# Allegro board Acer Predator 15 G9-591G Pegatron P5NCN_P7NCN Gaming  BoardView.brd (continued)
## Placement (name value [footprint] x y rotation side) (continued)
C7829  -  [VX_C0402_SMALL]  139.24 127.78 270 bottom
C7830  -  [VX_C0402_SMALL]  146.8 143.74 270 top
C7831  -  [VX_C0402_SMALL]  146.71 127.85 180 top
C7832  -  [VX_C0402_SMALL]  149.53 123.33 0 top
C7833  -  [VX_C0402_SMALL]  149.53 121.93 0 top
C7834  -  [VX_C0402_SMALL]  150.84 123.99 270 top
C7835  -  [VX_C0402_SMALL]  154.36 127.65 0 top
C7836  -  [VX_C0603_SMALL]  155.96 120.46 0 bottom
C7837  -  [VX_C0603_SMALL]  155.88 119.85 0 top
C7900  -  [VX_C0402_SMALL]  118.54 99.17 270 top
C7903  -  [VX_C0402_SMALL]  125.2 105.93 0 top
C7904  -  [VX_C0402_SMALL]  130.1 99.33 90 top
C7905  -  [VX_C0402_SMALL]  125.2 107.28 0 top
C7906  -  [VX_C0402_SMALL]  127.31 114.95 270 bottom
C7907  -  [VX_C0402_SMALL]  132 99.33 90 top
C7908  -  [VX_C0402_SMALL]  136.07 99.28 90 top
C7909  -  [VX_C0402_SMALL]  139.29 102.51 90 top
C7910  -  [VX_C0402_SMALL]  133.53 102.99 270 top
C7911  -  [VX_C0402_SMALL]  134.67 99.33 90 top
C7912  -  [VX_C0402_SMALL]  128.32 99.33 90 top
C7913  -  [VX_C0402_SMALL]  133.76 108.94 90 top
C7914  -  [VX_C0402_SMALL]  143.74 128.95 180 top
C7915  -  [VX_C0402_SMALL]  133.53 101.36 90 top
C7916  -  [VX_C0402_SMALL]  128.14 114.95 270 bottom
C7917  -  [VX_C0402_SMALL]  125.53 101.61 0 top
C7918  -  [VX_C0402_SMALL]  127.84 105.71 270 top
C7919  -  [VX_C0402_SMALL]  125.63 100.34 0 top
C7920  -  [VX_C0603_SMALL]  135.22 107.21 90 top
C7921  -  [VX_C0603_SMALL]  131.33 110.97 90 top
C7922  -  [VX_C0402_SMALL]  122.89 99.18 90 top
C7923  -  [VX_C0402_SMALL]  114.22 104.41 270 top
C7924  -  [VX_C0402_SMALL]  119.99 103.42 90 top
C7925  -  [VX_C0402_SMALL]  121.77 110.43 270 top
C7926  -  [VX_C0402_SMALL]  118.29 101.49 90 top
C7927  -  [VX_C0402_SMALL]  114.43 106 0 top
C7928  -  [VX_C0402_SMALL]  115.28 112.23 270 top
C7929  -  [VX_C0402_SMALL]  141.59 141.99 180 top
C7930  -  [VX_C0402_SMALL]  118.29 104.54 270 top
C7931  -  [VX_C0402_SMALL]  119.94 101.57 90 top
C7932  -  [VX_C0402_SMALL]  112.71 109.73 90 top
C7933  -  [VX_C0402_SMALL]  114.52 107.81 0 top
C7934  -  [VX_C0402_SMALL]  119.94 99.2 90 top
C7935  -  [VX_C0402_SMALL]  124.41 99.18 90 top
C7936  -  [VX_C0603_SMALL]  111.94 100.6 270 bottom
C7937  -  [VX_C0603_SMALL]  111.9 111.14 270 bottom
C8000  -  [VX_C0402_SMALL]  11.23 178.96 180 top
C8001  -  [VX_C0402_SMALL]  5 175.78 180 top
C8002  -  [VX_C0402_SMALL]  7.29 178.2 0 top
C8003  -  [VX_C0402_SMALL]  5 174.89 180 top
C8004  -  [VX_C0402_SMALL]  4.71 175.13 90 bottom
C8005  -  [VX_C0402_SMALL]  2.59 176.42 0 bottom
C8006  -  [VX_C0402_SMALL]  2.85 175.78 180 top
C8007  -  [VX_C0402_SMALL]  2.59 178.45 0 top
C8008  -  [VX_C0402_SMALL]  2.59 179.34 0 top
C8009  -  [VX_C0402_SMALL]  16.58 180.08 0 bottom
C8010  -  [VX_C0402_SMALL]  12.75 184.8 90 bottom
C8011  -  [VX_C0402_SMALL]  6.53 171.59 270 bottom
C8012  -  [VX_C0402_SMALL]  2.59 175.53 0 bottom
C8013  -  [VX_C0402_SMALL]  20.88 176.93 270 bottom
C8014  -  [VX_C0402_SMALL]  15.42 184.8 90 bottom
C8015  -  [VX_C0402_SMALL]  15.81 181.05 0 bottom
C8016  -  [VX_C0402_SMALL]  16.31 184.8 90 bottom
C8017  -  [VX_C0402_SMALL]  8.94 171.59 270 bottom
C8018  -  [VX_C0402_SMALL]  10.72 171.39 90 bottom
C8019  -  [VX_C0402_SMALL]  7.42 171.59 270 bottom
C8020  -  [VX_C0402_SMALL]  1.58 171.08 90 bottom
C8021  -  [VX_C0402_SMALL]  17.69 177.99 270 bottom
C8022  -  [VX_C0402_SMALL]  17.2 176.54 0 bottom
C8023  -  [VX_C0402_SMALL]  18.78 176.54 0 bottom
C8024  -  [VX_C0402_SMALL]  10.03 176.04 270 top
C8025  -  [VX_C0402_SMALL]  8.94 177.31 0 top
C8026  -  [VX_C0402_SMALL]  3.73 171.08 270 bottom
C8027  -  [VX_C0402_SMALL]  21.13 175.15 90 bottom
C8028  -  [VX_C0402_SMALL]  20.24 175.15 270 bottom
C8029  -  [VX_C0402_SMALL]  21.6 173.88 180 bottom
C8030  -  [VX_C0402_SMALL]  18.85 174.64 180 bottom
C8031  -  [VX_C0402_SMALL]  17.07 170.7 90 bottom
C8032  -  [VX_C0402_SMALL]  15.93 171.97 0 bottom
C8033  -  [VX_C0402_SMALL]  13.16 178.15 0 top
C8034  -  [VX_C0402_SMALL]  25.71 175.53 180 bottom
C8035  -  [VX_C0402_SMALL]  15.16 173.37 90 bottom
C8036  -  [VX_C0402_SMALL]  23.39 175.27 180 bottom
C8050  -  [VX_C0805_H57_SMALL]  37.9 173.24 90 bottom
C8051  -  [VX_C0805_H57_SMALL]  37.14 173.24 90 top
C8052  -  [VX_C0805_H57_SMALL]  38.91 173.24 90 top
C8053  -  [VX_C0402_SMALL]  39.29 172.99 90 bottom
C8054  -  [VX_C0402_SMALL]  42.72 173.88 270 bottom
C8055  -  [VX_C0402_SMALL]  31.8 174.13 270 bottom
C8056  -  [VX_C0805_H57_SMALL]  26.09 172.68 90 top
C8057  -  [VX_C0805_H57_SMALL]  27.86 172.68 90 top
C8058  -  [VX_C0805_H57_SMALL]  28.12 172.68 90 bottom
C8059  -  [VX_C0402_SMALL]  29.52 172.61 90 bottom
C8060  -  [VX_C0402_SMALL]  65.71 169.81 270 bottom
C8061  -  [VX_C0805_H57_SMALL]  60.12 168.54 90 top
C8062  -  [VX_C0805_H57_SMALL]  61.9 168.54 90 top
C8063  -  [VX_C0805_H57_SMALL]  60.63 168.42 90 bottom
C8064  -  [VX_C0402_SMALL]  62.03 168.16 90 bottom
C8065  -  [VX_C0402_SMALL]  44.12 174.64 0 bottom
C8066  -  [VX_C0402_SMALL]  33.2 174.77 0 bottom
C8067  -  [VX_C0402_SMALL]  66.3 172.45 0 bottom
C8068  -  [VX_C0402_H26_SMALL]  46.03 174 90 bottom
C8069  -  [VX_C0402_H26_SMALL]  34.85 173.88 90 bottom
C8070  -  [VX_C0402_H26_SMALL]  70.64 168.79 90 top
C8071  -  [VX_C0603_SMALL]  43.1 170.19 180 bottom
C8072  -  [VX_C0603_SMALL]  30.15 170.45 180 bottom
C8073  -  [VX_C0603_SMALL]  60.38 163.67 180 top
C8074  -  [VX_C0603_H39_SMALL]  57.96 160.29 270 top
C8075  -  [VX_C0603_H39_SMALL]  61.9 158 180 bottom
C8076  -  [VX_C0603_H39_SMALL]  61.9 156.73 180 bottom
C8077  -  [VX_C0603_H39_SMALL]  59.23 160.29 270 top
C8078  -  [VX_C0603_H39_SMALL]  52.76 138.83 180 top
C8079  -  [VX_C0603_H39_SMALL]  45.09 142.59 0 top
C8080  -  [VX_C0603_H39_SMALL]  47.7 142.64 180 top
C8081  -  [VX_C0603_H39_SMALL]  52.76 141.37 180 top
C8082  -  [VX_C0603_H39_SMALL]  47.7 141.37 180 top
C8083  -  [VX_C0603_H39_SMALL]  49.96 142.64 0 top
C8084  -  [VX_C0603_H39_SMALL]  52.76 142.64 180 top
C8085  -  [VX_C0603_H39_SMALL]  49.96 141.37 0 top
C8086  -  [VX_C0402_SMALL]  68.12 168.92 90 bottom
C8087  -  [VX_C0805_H57_SMALL]  89.84 171.59 90 bottom
C8088  -  [VX_C0805_H57_SMALL]  91.62 171.59 90 bottom
C8089  -  [VX_C0805_H57_SMALL]  93.4 171.59 90 bottom
C8090  -  [VX_C0402_SMALL]  88.19 170.96 180 bottom
C8091  -  [VX_C0603_H39_SMALL]  40.44 164.48 270 bottom
C8092  -  [VX_C0603_H39_SMALL]  52.88 158 270 top
C8093  -  [VX_C0603_H39_SMALL]  49.33 154.83 0 top
C8094  -  [VX_C0603_H39_SMALL]  60.5 160.03 270 bottom
C8095  -  [VX_C0603_H39_SMALL]  61.77 160.03 270 bottom
C8096  -  [VX_C0603_H39_SMALL]  45.09 141.32 0 top
C8097  -  [VX_C0603_H39_SMALL]  45.09 140.05 0 top
C8098  -  [VX_C0603_H39_SMALL]  41.68 164.48 270 bottom
C8099  -  [VX_C0603_H39_SMALL]  47.7 138.83 180 top
C8100  -  [VX_C0402_SMALL]  218.87 70.5 90 top
C8101  -  [VX_C0603_SMALL]  217.73 70.5 270 top
C8102  -  [VX_C0805_H57_SMALL]  206.38 57.77 0 bottom
C8103  -  [VX_C0402_SMALL]  206.4 59.27 0 bottom
C8104  -  [VX_C0805_H57_SMALL]  217.22 64.28 270 bottom
C8105  -  [VX_C0805_H57_SMALL]  215.44 64.28 270 bottom
C8106  -  [VX_C0402_SMALL]  218.49 64.28 270 bottom
C8107  -  [VX_C0603_SMALL]  222.81 74.69 180 top
C8108  -  [VX_C0603_SMALL]  213.54 74.82 180 top
C8109  -  [VX_C0402_SMALL]  232 81.52 270 bottom
C8110  -  [VX_C0402_SMALL]  193.22 71.64 0 bottom
C8111  -  [VX_C0402_SMALL]  220.93 69.82 90 bottom
C8112  -  [VX_C0402_SMALL]  203.38 63.77 180 bottom
C8113  -  [VX_C0402_SMALL]  220.4 78.12 0 top
C8114  -  [VX_C0402_SMALL]  216.33 77.99 0 top
C8115  -  [VX_C0402_SMALL]  220.78 80.66 270 top
C8116  -  [VX_C0402_SMALL]  215.95 80.53 90 top
C8117  -  [VX_C0402_SMALL]  218.24 78.12 0 top
C8118  -  [VX_C0402_SMALL]  213.16 77.36 180 top
C8119  -  [VX_C0603_SMALL]  241.73 65.8 90 top
C8120  -  [VX_C0603_SMALL]  244.78 68.34 0 top
C8121  -  [VX_C0603_SMALL]  246.3 65.42 90 top
C8122  -  [VX_C0603_SMALL]  247.83 68.34 0 top
C8123  -  [VX_C0603_SMALL]  251 65.55 90 top
C8124  -  [VX_C0402_SMALL]  213.9 48.31 180 bottom
C8125  -  [VX_C0402_SMALL]  213.56 40.75 180 bottom
C8126  -  [VX_C0402_SMALL]  199.8 65.98 90 top
C8127  -  [VX_C0402_SMALL]  208.48 79.57 180 top
C8128  -  [VX_C0402_SMALL]  213.56 41.62 180 bottom
C8129  -  [VX_C0402_SMALL]  213.9 49.46 180 bottom
C8130  -  [VX_C0402_SMALL]  236.09 65.9 90 top
C8131  -  [VX_C0402_SMALL]  236.98 65.9 90 top
C8202  -  [VX_C0402_SMALL]  135.81 72.36 270 bottom
C8203  -  [VX_C0805_H57_SMALL]  128.6 66.57 0 bottom
C8205  -  [VX_C0603_SMALL]  136.7 68.09 270 bottom
C8206  -  [VX_C0402_SMALL]  136.96 75.28 0 bottom
C8207  -  [VX_C0603_SMALL]  142.55 70.45 270 bottom
C8208  -  [VX_C0402_SMALL]  140.39 76.55 0 bottom
C8209  -  [VX_C0603_H39_SMALL]  154.91 72.99 90 bottom
C8210  -  [VX_C0603_H39_SMALL]  153.7 72.99 90 bottom
C8211  -  [VX_C0603_H39_SMALL]  152.48 72.99 90 bottom
C8212  -  [VX_C0603_H39_SMALL]  147.5 66.9 180 bottom
C8213  -  [VX_C0603_H39_SMALL]  151.26 72.99 90 bottom
C8214  -  [VX_C0402_SMALL]  134.93 72.36 270 bottom
C8215  -  [VX_C0402_SMALL]  127.81 67.96 0 bottom
C8216  -  [VX_C0402_SMALL]  146.73 69.02 0 bottom
C8300  -  [VX_C0603_SMALL]  132.26 58.56 0 top
C8301  -  [VX_C0603_SMALL]  132.26 57.29 0 top
C8302  -  [VX_C0402_SMALL]  130.73 59.7 0 top
C8303  -  [VX_C0402_SMALL]  136.13 59.02 180 top
C8304  -  [VX_C0402_SMALL]  125.13 70.39 90 bottom
C8305  -  [VX_C0402_SMALL]  124.24 70.39 90 bottom
C8306  -  [VX_C0805_H57_SMALL]  128.07 67.32 90 top
C8307  -  [VX_C0805_H57_SMALL]  126.4 69.88 90 bottom
C8308  -  [VX_C0603_SMALL]  130.61 61.23 270 top
C8309  -  [VX_C0603_SMALL]  130.48 65.42 0 top
C8310  -  [VX_C0402_SMALL]  137.85 64.78 270 top
C8311  -  [VX_C0603_H39_SMALL]  115.37 74.06 90 top
C8312  -  [VX_C0603_H39_SMALL]  111.56 74.06 90 top
C8313  -  [VX_C0603_H39_SMALL]  115.77 68.7 270 top
C8314  -  [VX_C0402_SMALL]  123.38 70.39 90 bottom
C8315  -  [VX_C0603_H39_SMALL]  114.1 74.06 90 top
C8316  -  [VX_C0603_H39_SMALL]  112.83 74.06 90 top
C8317  -  [VX_C0603_H39_SMALL]  117.04 68.7 270 top
C8318  -  [VX_C0402_SMALL]  134.93 66.56 0 top
C8319  -  [VX_C0402_SMALL]  138.1 61.61 180 top
C8320  -  [VX_C0402_SMALL]  138.1 58.94 0 top
C8321  -  [VX_C0402_SMALL]  139.88 58.94 180 top
C8322  -  [VX_C0402_SMALL]  138.1 62.5 180 top
C8323  -  [VX_C0402_SMALL]  119.43 21.89 0 top
C8324  -  [VX_C0402_SMALL]  136.83 61.86 180 bottom
C8325  -  [VX_C0402_SMALL]  108.66 75.25 180 top
C8326  -  [VX_C0402_SMALL]  108.66 74.36 180 top
C8327  -  [VX_C0402_SMALL]  132.21 56.25 180 top
C8328  -  [VX_C0402_SMALL]  132.21 55.36 180 top
C8400  -  [VX_C0402_SMALL]  168.2 26 90 top
C8401  -  [VX_C0603_SMALL]  171.7 27.95 0 top
C8402  -  [VX_C0402_SMALL]  174.12 22.78 90 top
C8403  -  [VX_C0402_SMALL]  174.63 25.59 180 top
C8404  -  [VX_C0603_SMALL]  175.31 26.68 0 top
C8405  -  [VX_C0402_SMALL]  170.08 28.31 270 top
C8406  -  [VX_C0402_SMALL]  167.06 29.56 180 top
C8700  -  [VX_C0402_SMALL]  154.36 87.98 90 bottom
C8701  -  [VX_C0402_SMALL]  119.69 79.72 90 top
C8702  -  [VX_C0805_H57_SMALL]  122.23 79.21 90 top
C8703  -  [VX_C0603_SMALL]  120.7 79.6 270 top
C8704  -  [VX_C0805_H57_SMALL]  124 79.21 90 top
C8706  -  [VX_C0402_SMALL]  146.45 83.48 180 bottom
C8707  -  [VX_C0603_SMALL]  148.13 88.61 90 bottom
C8708  -  [VX_C0402_SMALL]  120.13 80.47 0 bottom
C8709  -  [VX_C0402_SMALL]  153.09 85.24 0 bottom
C8710  -  [VX_C0603_H39_SMALL]  144.27 106.77 180 top
C8711  -  [VX_C0603_H39_SMALL]  98.7 108.12 0 top
C8712  -  [VX_C0603_H39_SMALL]  98.7 106.85 0 top
C8713  -  [VX_C0603_H39_SMALL]  138.61 92.34 90 top
C8714  -  [VX_C0603_H39_SMALL]  98.68 109.39 0 top
C8715  -  [VX_C0603_H39_SMALL]  97.49 148.71 0 top
C8716  -  [VX_C0603_H39_SMALL]  134.8 92.34 90 top
C8717  -  [VX_C0603_H39_SMALL]  136.07 92.34 90 top
C8718  -  [VX_C0603_H39_SMALL]  137.34 92.34 90 top
C8719  -  [VX_C0603_H39_SMALL]  144.27 105.5 180 top
C8720  -  [VX_C0603_H39_SMALL]  144.32 109.31 180 top
C8721  -  [VX_C0603_H39_SMALL]  144.27 108.04 180 top
C8722  -  [VX_C0603_H39_SMALL]  144.27 104.23 180 top
C8723  -  [VX_C0402_SMALL]  158.67 83.28 90 bottom
C8724  -  [VX_C0402_SMALL]  156.06 79.9 180 bottom
C8725  -  [VX_C0402_SMALL]  157.02 83.78 270 bottom
C8726  -  [VX_C0402_SMALL]  156.13 84.6 270 bottom
C8727  -  [VX_C0603_SMALL]  149.78 80.28 270 top
C8728  -  [VX_C0402_SMALL]  132.39 81.75 90 top
C8729  -  [VX_C0603_SMALL]  132.86 76.69 180 top
C8730  -  [VX_C0805_H57_SMALL]  133.27 78.2 0 top
C8731  -  [VX_C0805_H57_SMALL]  133.27 79.98 0 top
C8733  -  [VX_C0402_SMALL]  145.6 78.53 270 bottom
C8735  -  [VX_C0402_SMALL]  137.62 76.67 90 bottom
C8736  -  [VX_C0402_SMALL]  143.04 95.26 270 top
C8737  -  [VX_C0402_SMALL]  156.9 105.88 180 top
C8738  -  [VX_C0603_SMALL]  157.15 101.19 0 top
C8739  -  [VX_C0805_H57_SMALL]  157.15 104.49 180 top
C8740  -  [VX_C0805_H57_SMALL]  157.15 102.66 180 top
C8741  -  [VX_C0402_H28_SMALL]  147.5 98.14 180 top
C8742  -  [VX_C0402_SMALL]  156 107.6 180 bottom
C8743  -  [VX_C0402_SMALL]  128.65 96.76 270 top
C8744  -  [VX_C0402_SMALL]  129.62 96.77 270 top
C8745  -  [VX_C0603_SMALL]  123.11 67.53 90 top
C8746  -  [VX_C0603_SMALL]  121.99 75.97 0 top
C8747  -  [VX_C0402_SMALL]  120.4 75.79 270 top
C8748  -  [VX_C0603_SMALL]  124.51 72.28 270 top
C8800  -  [VX_C0402_SMALL]  9.7 113.38 270 top
C8801  -  [VX_C0402_SMALL]  9.32 114.65 180 top
C8802  -  [VX_C0402_SMALL]  253.42 18.64 90 top
C8803  -  [VX_C0805_H57_SMALL]  222.94 16.35 90 top
C8804  -  [VX_C0402_SMALL]  228.8 17.29 270 top
C8806  -  [VX_C1206_H49]  8.05 109.29 270 top
C8807  -  [VX_C0402_SMALL]  224 33.75 180 top
C8808  -  [VX_C0402_SMALL]  223.24 32.48 270 top
C8809  -  [VX_C0402_SMALL]  224.64 32.48 270 top
C8810  -  [VX_C0402_SMALL]  229.69 17.29 90 top
C8811  -  [VX_C0805_H57_SMALL]  224.71 16.35 90 top
C8812  -  [VX_C0805_H57_SMALL]  226.49 16.35 90 top
C8813  -  [VX_C0402_SMALL]  227.89 17.32 90 top
C8814  -  [VX_C0402_SMALL]  218.49 29.94 90 top
C8815  -  [VX_C0402_SMALL]  214.55 29.38 180 top
C8816  -  [VX_C0603_SMALL]  225.6 29.76 180 top
C8817  -  [VX_C0402_SMALL]  227 28.59 180 top
C8818  -  [VX_C0805_H57_SMALL]  252.65 12.16 90 top
C8819  -  [VX_C0805_H57_SMALL]  249.1 12.16 90 top
C8820  -  [VX_C0805_H57_SMALL]  250.88 12.16 90 top
C8821  -  [VX_C0603_SMALL]  226.12 25.75 0 top
C8822  -  [VX_C0402_SMALL]  230.56 17.29 90 top
C8823  -  [VX_C0402_SMALL]  232.33 25.06 90 top
C8824  -  [VX_C0402_SMALL]  216.39 24.86 270 top
C8825  -  [VX_C0402_SMALL]  230.43 25.7 0 top
C8826  -  [VX_C0402_SMALL]  230.43 24.3 0 top
C8827  -  [VX_C0402_SMALL]  217.98 37.3 270 top
C8828  -  [VX_C0805_H57_SMALL]  219.25 44.42 180 bottom
C8829  -  [VX_C0402_SMALL]  221.03 39.08 90 bottom
C8830  -  [VX_C0402_SMALL]  218.62 36.54 90 bottom
C8831  -  [VX_C0402_SMALL]  214.55 28.54 0 top
C8832  -  [VX_C0402_SMALL]  221.71 32.99 90 bottom
C8900  -  [VX_C0402_SMALL]  162.02 85.26 90 top
C8901  -  [VX_C0805_H57_SMALL]  172.77 86.33 180 top
C8902  -  [VX_C0805_H57_SMALL]  160.71 84.88 90 top
C8903  -  [VX_C0402_SMALL]  176 83.28 180 top
C8904  -  [VX_C0402_SMALL]  178.99 81.55 180 top
C8905  -  [VX_C0402_SMALL]  159.18 95.98 270 top
C8906  -  [VX_C0402_SMALL]  172.1 83.02 180 top
C8907  -  [VX_C0402_SMALL]  178.73 88.49 90 top
C8908  -  [VX_C0402_SMALL]  184.96 85.23 180 top
C8909  -  [VX_C0402_SMALL]  185.03 83.35 180 top
C8910  -  [VX_C0603_SMALL]  175.31 87.39 270 top
C8912  -  [VX_C0402_SMALL]  179.79 88.46 270 top
C8915  -  [VX_C0402_SMALL]  180.63 88.14 270 top
C8916  -  [VX_C0402_SMALL]  143.45 121.14 180 top
C8917  -  [VX_C0402_SMALL]  160.07 87.85 90 bottom
C09100  -  [VX_C0201_H14]  33.45 136.87 0 top
C9100  -  [VX_C0402_SMALL]  141.58 65.6 180 bottom
C09101  -  [VX_C0201_H14]  28.5 143.65 0 top
C9101  -  [VX_C0402_H26_SMALL]  141.4 60.72 90 bottom
C9102  -  [VX_C0402_SMALL]  149.4 48.61 90 top
C09102  -  [VX_C0201_H14]  37.52 144.41 0 top
C09103  -  [VX_C0201_H14]  33.2 147.46 180 top
C9103  -  [VX_C0402_SMALL]  144.63 65.88 270 bottom
C9104  -  [VX_C0402_SMALL]  154.23 46.83 180 top
C09104  -  [VX_C0201_H14]  34.34 145.18 180 top
C09105  -  [VX_C0201_H14]  32.82 144.41 0 top
C9105  -  [VX_C0402_SMALL]  143.8 65.88 270 bottom
C09106  -  [VX_C0201_H14]  37.52 143.65 0 top
C09107  -  [VX_C0201_H14]  35.61 147.46 0 top
C9107  -  [VX_C0402_H26_SMALL]  146.23 62.96 90 bottom
C09108  -  [VX_C0201_H14]  37.92 147.46 180 top
C9108  -  [VX_C0402_SMALL]  144.22 59.5 180 bottom
C09109  -  [VX_C0201_H14]  37.52 145.18 0 top
C9109  -  [VX_C0402_SMALL]  142.62 59.5 0 bottom
C09110  -  [VX_C0201_H14]  38.28 136.84 0 top
C9110  -  [VX_C0402_SMALL]  146.23 61.36 270 bottom
C09111  -  [VX_C0201_H14]  38.28 136.08 0 top
C9111  -  [VX_C0402_SMALL]  195.9 70.75 270 bottom
C9112  -  [VX_C0402_SMALL]  198.55 66.05 180 top
C09112  -  [VX_C0201_H14]  40.82 136.16 0 top
C09113  -  [VX_C0201_H14]  39.04 143.65 180 top
C9113  -  [VX_C0402_SMALL]  193.07 66.69 270 top
C9114  -  [VX_C0402_SMALL]  195.76 70.63 270 top
C09114  -  [VX_C0201_H14]  33.45 134.58 0 top
C9115  -  [VX_C0402_SMALL]  193.22 68.47 90 top
C09115  -  [VX_C0201_H14]  30.66 135.27 180 top
C09116  -  [VX_C0201_H14]  28.5 149.37 180 top
C9116  -  [VX_C0402_SMALL]  195 63.9 90 top
C09117  -  [VX_C0201_H14]  33.2 149.37 180 top
C9117  -  [VX_C0402_SMALL]  195.89 63.9 90 top
C09118  -  [VX_C0201_H14]  40.31 149.37 0 top
C9118  -  [VX_C0402_SMALL]  220.65 86.12 180 bottom
C09119  -  [VX_C0201_H14]  28.5 142.13 0 top
C9119  -  [VX_C0402_SMALL]  216.26 88.03 180 bottom
C09120  -  [VX_C0201_H14]  30.02 142.89 180 top
C9120  -  [VX_C0402_SMALL]  220.65 84.85 180 bottom
C09121  -  [VX_C0201_H14]  37.52 142.89 0 top
C9121  -  [VX_C0402_SMALL]  218.26 82.59 0 bottom
C09122  -  [VX_C0201_H14]  28.5 145.18 0 top
C9122  -  [VX_C0402_SMALL]  217.86 88.03 0 bottom
C09123  -  [VX_C0201_H14]  34.34 142.89 180 top
C9123  -  [VX_C0402_SMALL]  214.17 84.98 0 bottom
C09124  -  [VX_C0201_H14]  33.45 135.35 0 top
C9124  -  [VX_C0402_SMALL]  214.17 85.99 0 bottom
C09125  -  [VX_C0201_H14]  36.25 135.4 180 top
C9125  -  [VX_C0402_SMALL]  216.56 82.59 180 bottom
C09126  -  [VX_C0201_H14]  36.25 134.67 180 top
C9126  -  [VX_C0402_SMALL]  237.54 63.9 0 top
C09127  -  [VX_C0201_H14]  32.82 142.89 0 top
C9127  -  [VX_C0402_SMALL]  239.32 61.08 180 top
C09128  -  [VX_C0201_H14]  28.5 144.41 0 top
C9128  -  [VX_C0402_SMALL]  233.17 61.25 0 bottom
C9129  -  [VX_C0402_SMALL]  239.32 61.99 180 top
C09129  -  [VX_C0201_H14]  37.92 149.37 180 top
C09130  -  [VX_C0201_H14]  32.82 143.65 0 top
C9130  -  [VX_C0402_SMALL]  235.13 63.9 180 top
C9131  -  [VX_C0402_SMALL]  237.67 59.22 0 top
C9132  -  [VX_C0402_SMALL]  235.26 59.22 180 top
C9133  -  [VX_C0402_SMALL]  196.52 82.14 270 top
C9134  -  [VX_C0402_SMALL]  198.17 82.14 270 top
C9200  -  [VX_C0402_SMALL]  136.45 49.98 0 top
C9400  -  [VX_C0402_SMALL]  81.08 158.13 90 bottom
C9401  -  [VX_C0805_H57_SMALL]  84.25 158.38 90 bottom
C9402  -  [VX_C0805_H57_SMALL]  82.47 158.38 90 bottom
C9403  -  [VX_C0402_SMALL]  79.55 154.4 0 bottom
C9405  -  [VX_C0603_SMALL]  73.17 160.87 0 bottom
C9406  -  [VX_C0603_H39_SMALL]  65.96 162.07 90 bottom
C9407  -  [VX_C0603_H39_SMALL]  70.92 162.07 90 bottom
C9408  -  [VX_C0603_H39_SMALL]  67.23 162.07 90 bottom
C9409  -  [VX_C0603_H39_SMALL]  68.5 162.07 90 bottom
C9410  -  [VX_C0603_H39_SMALL]  69.77 162.07 90 bottom
C9411  -  [VX_C0402_SMALL]  78.66 158 90 top
C9412  -  [VX_C0402_SMALL]  79.55 152.62 180 bottom
C9414  -  [VX_C0402_SMALL]  73.2 148.1 180 bottom
C9415  -  [VX_C0402_SMALL]  73.2 148.99 180 bottom
C9416  -  [VX_C0402_SMALL]  71.81 153 180 bottom
C9500  -  [VX_C0402_SMALL]  123.11 60.97 90 bottom
C9501  -  [VX_C0805_H57_SMALL]  126.16 60.97 90 bottom
C9502  -  [VX_C0805_H57_SMALL]  124.38 60.97 90 bottom
C9503  -  [VX_C0402_SMALL]  120.07 58.39 180 top
C9504  -  [VX_C0402_SMALL]  117.87 64.11 0 top
C9505  -  [VX_C0603_SMALL]  120.57 61.23 0 top
C9506  -  [VX_C0603_H39_SMALL]  109.02 65.67 90 top
C9507  -  [VX_C0603_H39_SMALL]  110.29 65.67 90 top
C9508  -  [VX_C0603_H39_SMALL]  111.56 65.67 90 top
C9509  -  [VX_C0603_H39_SMALL]  107.82 66.05 90 bottom
C9510  -  [VX_C0603_H39_SMALL]  109.09 66.05 90 bottom
C9511  -  [VX_C0402_SMALL]  124.62 64.39 0 top
C9512  -  [VX_C0402_SMALL]  123.09 59.55 180 top
C9513  -  [VX_C0402_SMALL]  117.98 66.26 90 top
C9514  -  [VX_C0402_SMALL]  108 65.67 270 top
C9515  -  [VX_C0402_SMALL]  107.11 65.67 270 top
C9600  -  [VX_C0603_H39_SMALL]  92.38 174.97 0 top
C9601  -  [VX_C0402_SMALL]  90.86 176.62 90 top
C9602  -  [VX_C0603_H39_SMALL]  89.71 169.26 270 top
C9603  -  [VX_C0402_SMALL]  75.74 178.02 90 bottom
C9604  -  [VX_C0805_H57_SMALL]  79.5 174.85 0 top
C9605  -  [VX_C0805_H57_SMALL]  78.92 172.43 90 top
C9606  -  [VX_C0402_SMALL]  93.4 165.57 180 top
C9607  -  [VX_C0402_SMALL]  92.51 176.12 180 top
C9608  -  [VX_C0402_SMALL]  84 169.38 180 top
C9609  -  [VX_C0603_SMALL]  86.92 175.48 180 top
C9610  -  [VX_C0402_SMALL]  80.19 172.31 90 top
C9611  -  [VX_C0402_SMALL]  87.55 170.02 180 top
C9612  -  [VX_C0402_SMALL]  83.11 175.86 270 top
C9613  -  [VX_C0603_H39_SMALL]  92.38 172.43 0 top
C9614  -  [VX_C0603_H39_SMALL]  92.38 173.7 0 top
C75001  -  [VX_C0603_SMALL]  113.81 145.19 0 top
C75002  -  [VX_C0603_SMALL]  113.81 133.76 0 top
C75003  -  [VX_C0402_SMALL]  101.14 153.26 270 top
C75004  -  [VX_C0402_SMALL]  110.03 147.21 0 top
C75005  -  [VX_C0402_SMALL]  93.52 159.94 180 top
C75006  -  [VX_C0603_SMALL]  110.19 136.29 180 top
C75007  -  [VX_C0402_SMALL]  116.13 148.99 0 top
C75008  -  [VX_C0402_SMALL]  108 147.21 180 top
C75009  -  [VX_C0603_SMALL]  100.01 148.64 180 top
C75010  -  [VX_C0402_SMALL]  110.03 148.1 0 top
C75011  -  [VX_C0402_SMALL]  110.03 146.32 0 top
C75012  -  [VX_C0402_SMALL]  108 148.1 180 top
C75013  -  [VX_C0402_SMALL]  108 148.99 180 top
C75014  -  [VX_C0603_SMALL]  102.18 142.76 180 top
C75015  -  [VX_C0603_SMALL]  110.19 142.64 180 top
C75016  -  [VX_C0402_SMALL]  110.03 148.99 0 top
C75017  -  [VX_C0402_SMALL]  94.84 151.42 90 top
C75018  -  [VX_C0402_SMALL]  113.97 146.32 180 top
C75019  -  [VX_C0402_SMALL]  116.13 148.1 0 top
C75020  -  [VX_C0603_SMALL]  110.19 140.1 180 top
C75021  -  [VX_C0402_SMALL]  95.73 151.42 90 top
C75022  -  [VX_C0402_SMALL]  116.12 147.19 0 top
C75023  -  [VX_C0402_SMALL]  113.97 148.1 180 top
C75024  -  [VX_C0402_SMALL]  116.12 146.3 0 top
C75025  -  [VX_C0402_SMALL]  113.97 148.99 180 top
C75026  -  [VX_C0402_SMALL]  100.14 138.91 90 top
C75027  -  [VX_C0402_SMALL]  113.97 147.21 180 top
C80002  -  [VX_C0603_H39_SMALL]  52.76 140.1 180 top
C80004  -  [VX_C0603_H39_SMALL]  36.12 151.53 180 top
C80005  -  [VX_C0805_H57_SMALL]  12.88 168.54 180 top
C80006  -  [VX_C0805_H57_SMALL]  17.07 169.18 90 top
C80008  -  [VX_C0603_H39_SMALL]  40.69 137.94 180 top
C80009  -  [VX_C0603_H39_SMALL]  16.86 158.51 270 bottom
C80010  -  [VX_C0603_H39_SMALL]  15.59 158.51 270 bottom
C80012  -  [VX_C0603_H39_SMALL]  27.86 157.75 270 bottom
C80013  -  [VX_C0603_H39_SMALL]  22.99 159.65 270 bottom
C80017  -  [VX_C0603_H39_SMALL]  30.4 137.8 0 top
C80019  -  [VX_C0402_SMALL]  9.83 166.51 0 bottom
C80020  -  [VX_C0603_H39_SMALL]  49.2 151.53 0 top
C80022  -  [VX_C0603_H39_SMALL]  32.69 151.53 0 top
C80023  -  [VX_C0603_H39_SMALL]  34.6 154.57 270 top
C80024  -  [VX_C0603_H39_SMALL]  21.77 159.65 270 bottom
C80025  -  [VX_C0402_H26_SMALL]  24.82 170.19 90 top
C80026  -  [VX_C0603_H39_SMALL]  49.96 140.1 0 top
C80027  -  [VX_C0402_SMALL]  5 164.48 90 top
C80029  -  [VX_C0603_H39_SMALL]  77.9 167.15 180 top
C80031  -  [VX_C0603_H39_SMALL]  57.13 150.23 180 top
C80032  -  [VX_C0603_H39_SMALL]  33.33 154.57 270 top
C80036  -  [VX_C0603_H39_SMALL]  45.54 151.53 180 top
C80038  -  [VX_C0603_H39_SMALL]  49.96 138.83 0 top
C80039  -  [VX_C0603_H39_SMALL]  36.33 154.84 0 top
C80040  -  [VX_C0603_H39_SMALL]  40.31 151.53 180 top
C80041  -  [VX_C0603_SMALL]  88.82 168.92 270 bottom
C80042  -  [VX_C0402_SMALL]  20.88 170.83 270 bottom
C80044  -  [VX_C0603_H39_SMALL]  55.17 146.06 0 top
C80046  -  [VX_C0603_SMALL]  2.59 158.38 0 top
C80049  -  [VX_C0603_H39_SMALL]  77.9 165.88 180 top
C80050  -  [VX_C0603_H39_SMALL]  54.15 158 270 top
C80052  -  [VX_C0402_SMALL]  8.56 165.75 270 bottom
C80055  -  [VX_C0603_H39_SMALL]  51.74 151.53 0 top
C80056  -  [VX_C0603_SMALL]  19.61 162.96 180 bottom
C80057  -  [VX_C0603_H39_SMALL]  29.01 151.53 180 top
C80059  -  [VX_C0603_H39_SMALL]  56.92 152.31 270 top
C80062  -  [VX_C0603_H39_SMALL]  33.07 157.32 270 bottom
C80064  -  [VX_C0402_SMALL]  22.28 171.46 0 bottom
C80066  -  [VX_C0402_H26_SMALL]  70.03 167.53 180 bottom
C80068  -  [VX_C0603_H39_SMALL]  32.06 154.57 270 top
C80069  -  [VX_C0603_H39_SMALL]  33.73 137.86 180 top
C80070  -  [VX_C0805_H57_SMALL]  3.73 164.02 90 top
C80073  -  [VX_C0603_H39_SMALL]  37.87 164.48 270 bottom
C80074  -  [VX_C0402_SMALL]  13.26 167.15 180 top
C80075  -  [VX_C0603_H39_SMALL]  45.09 138.78 0 top
C80076  -  [VX_C0805_H57_SMALL]  2.34 164.02 90 bottom
C80077  -  [VX_C0603_H39_SMALL]  34.34 158.3 270 bottom
C80078  -  [VX_C0603_H39_SMALL]  39.14 164.48 270 bottom
C80079  -  [VX_C0805_H57_SMALL]  1.96 164.02 90 top
C80082  -  [VX_C0402_H26_SMALL]  12.37 165.11 90 top
C80083  -  [VX_C0603_H39_SMALL]  47.7 140.1 180 top
C80087  -  [VX_C0603_H39_SMALL]  55.42 158 270 top
C80091  -  [VX_C0805_H57_SMALL]  15.29 169.18 90 top
C80092  -  [VX_C0603_H39_SMALL]  56.69 160.29 270 top
C80095  -  [VX_C0603_H39_SMALL]  35.97 137.86 0 top
C80098  -  [VX_C0603_H39_SMALL]  29.08 157.75 270 bottom
C80102  -  [VX_C0603_H39_SMALL]  18.09 158.51 270 bottom
C80103  -  [VX_C0402_SMALL]  3.61 183.28 0 top
C80104  -  [VX_C0402_SMALL]  2.08 182.51 180 bottom
C80105  -  [VX_C0402_SMALL]  3.48 182.01 90 bottom
C80106  -  [VX_C0402_SMALL]  4.22 178.56 0 bottom
C80107  -  [VX_C0603_SMALL]  8.81 182.39 180 top
C80108  -  [VX_C0402_H24_SMALL]  8.76 181.9 0 bottom
C80109  -  [VX_C0402_SMALL]  4.24 173.24 180 bottom
C80110  -  [VX_C0402_SMALL]  23.39 174.39 180 bottom
C80111  -  [VX_C0402_SMALL]  3.61 182.39 0 top
C80112  -  [VX_C0603_H39_SMALL]  38.57 153.14 180 top
C80113  -  [VX_C0603_H39_SMALL]  19.36 159.65 270 bottom
C80114  -  [VX_C0603_H39_SMALL]  20.5 159.65 270 bottom
C80115  -  [VX_C0603_H39_SMALL]  11.21 145.51 0 top
C80116  -  [VX_C0603_H39_SMALL]  24.21 159.65 270 bottom
C80117  -  [VX_C0603_H39_SMALL]  14.32 158.51 270 bottom
C80118  -  [VX_C0603_H39_SMALL]  13.05 158.51 270 bottom
C80119  -  [VX_C0603_H39_SMALL]  26.64 157.75 270 bottom
C80121  -  [VX_C0603_H39_SMALL]  25.43 159.65 270 bottom
C80122  -  [VX_C0402_SMALL]  55.02 137.43 0 top
C80123  -  [VX_C0402_SMALL]  54.99 138.34 0 top
C80124  -  [VX_C0402_SMALL]  21.64 151.14 90 top
C80125  -  [VX_C0402_SMALL]  22.53 151.14 90 top
C80126  -  [VX_C0402_SMALL]  54.92 147.46 0 top
C80127  -  [VX_C0402_SMALL]  54.94 149.47 0 top
C80128  -  [VX_C0603_H39_SMALL]  69.94 149.69 180 top
C80129  -  [VX_C0603_H39_SMALL]  55.17 151.53 0 top
C80130  -  [VX_C0603_H39_SMALL]  69.94 150.91 180 top
C80131  -  [VX_C0603_H39_SMALL]  69.94 152.15 180 top
C80132  -  [VX_C0603_H39_SMALL]  77.9 163.87 180 top
C80133  -  [VX_C0402_SMALL]  4.24 172.35 180 bottom
C80134  -  [VX_C0402_SMALL]  17.65 149.24 90 bottom
C80135  -  [VX_C0402_H28_SMALL]  73.46 54.75 0 bottom
CE1225  -  [VX_C3528]  255.45 22.57 90 top
CE1800  -  [VX_C7343D_H83]  35.1 108.98 0 top
CE5502  -  [VX_C3528]  256.24 52.16 90 top
CE5503  -  [VX_C3528]  255.58 63.21 90 top
CE6703  -  [VX_C3528]  13.21 103.01 90 top
CE7502  -  [VX_C7343D_3P]  134.58 138.44 270 top
CE8000  -  [VX_C7343D_3P]  46.79 158.38 180 top
CE8001  -  [VX_C7343D_3P]  33.2 158.59 0 top
CE8004  -  [VX_C7343D_3P]  16.43 157.75 270 top
CE8007  -  [VX_C7343D_3P]  8.69 149.11 0 top
CE8100  -  [VX_C7343D_H83]  229.08 82.62 270 bottom
CE8101  -  [VX_C7343D_H83]  193.09 75.2 0 bottom
CE8102  -  [VX_C7343D_H83]  224.08 82.56 270 bottom
CE8103  -  [VX_C7343D_H83]  193.09 80.28 0 bottom
CE8300  -  [VX_CESMD_260X260_PANASONIC]  130.86 72.1 270 bottom
CE8700  -  [VX_C7343D_3P]  145.11 105.12 180 bottom
CE8701  -  [VX_C7343D_3P]  109.91 100.6 270 top
CE8702  -  [VX_C7343D_3P]  136.88 91.71 90 bottom
CE8703  -  [VX_C7343D_3P]  105.72 109.23 180 top
CE8704  -  [VX_C7343D_3P]  104.32 129.39 90 top
CE8705  -  [VX_C7343D_3P]  86.16 158.34 0 top
CE8900  -  [VX_C7343D_3P]  166.29 91.28 180 top
CE8901  -  [VX_C7343D_3P]  168.07 91.28 180 bottom
CN1  -  [VX_C_ARRAY_8P_79X49_H39]  89.64 26.76 0 top
CN2  -  [VX_C_ARRAY_8P_79X49_H39]  92.43 26.76 0 top
CN3  -  [VX_C_ARRAY_8P_79X49_H39]  95.61 26.76 0 top
CN4  -  [VX_C_ARRAY_8P_79X49_H39]  98.73 26.76 0 top
CN5  -  [VX_C_ARRAY_8P_79X49_H39]  104.45 26.76 0 top
CN6  -  [VX_C_ARRAY_8P_79X49_H39]  107.62 26.76 0 top
CN7  -  [VX_C_ARRAY_8P_79X49_H39]  101.52 26.76 0 top
CON1  -  [VX_FPC_8P_20_2H_RA_ACE_B]  185.3 160.8 180 top
CON300  -  [VX_WTOB_4P_31_2H_RA]  174.4 147.75 0 top
CON302  -  [VX_WTOB_6P_31_2H]  164.55 148.7 270 top
CON400  -  [VX_WTOB_4P_31_2H_RA]  202.1 147.8 0 top
CON402  -  [VX_FPC_CON_28P_20_2H_AC_B]  188.45 180.5 180 top
CON1201  -  [T_NB_USB_24P_10HD_ACON]  266.85 26.05 90 top
CON1600  -  [VX_DDR4_260P_20_4HD_ARG]  67 73.2 0 top
CON1601  -  [VX_DDR4_260P_20_4HD_REV_ARG]  65 73.2 180 bottom
CON1700  -  [VX_DDR4_260P_20_4H_RE_H177]  67 61.2 180 top
CON1701  -  [VX_DDR4_260P_20_4H_REV_ARGO]  65 61.2 180 bottom
CON2800  -  [VX_BATHOLDER_2P_2HOLD]  246 53.9 270 bottom
CON3100  -  [VX_FPC_26P_39_2HOLD_RA]  103.55 28.3 180 bottom
CON3104  -  [VX_FPC_14P_20_2H_ACE_B]  178.7 26.75 180 bottom
CON3110  -  [VX_FPC_14P_20_2HD_RA_ENTERY]  137.5 24.8 180 bottom
CON3400  -  [VX_LAN_JACK_8P_2HD_SAN_LF2]  265.7 138.9 270 bottom
CON3600  -  [VX_WTOB_4P_39_2H_ACES]  14 112 180 bottom
CON3700  -  [VX_WTOB_4P_49_2HD_RA_ACES]  191.7 26.2 180 bottom
CON4301  -  [VX_WTOB_20P_20_6HOLD_ENTERY]  95.52 183.45 180 top
CON4400  -  [VX_FPC_12P_20_2HD_B]  72.38 27.45 180 bottom
CON4402  -  [VX_FPC_12P_20_2HD_B]  203.11 24.26 180 bottom
CON4500  -  [VX_WTOB_40P_20_6HD_STAR]  60.5 179.2 0 top
CON4601  -  [VX_DISPLAY_20P_39_4H_ACON]  268.02 116.95 90 top
CON4800  -  [VX_HDMI_19P_4H_SING]  269 93.85 90 top
CON5000  -  [VX_WTOB_4P_49_2HD_ACE]  27.01 111.7 180 bottom
CON5001  -  [VX_WTOB_4P_49_2HD_ACE]  180 75.95 0 bottom
CON5100  -  [VX_WTOB_20P_20_6HOLD_ENTERY]  39 33.4 90 bottom
CON5101  -  [VX_SATA_13P_4HLD_ALLTP]  21.38 30.95 90 bottom
CON5102  -  [VX_NGFF_67P_20_4HOLD_H165]  62.9 43.1 270 bottom
CON5103  -  [VX_MINI_PCI_67P_20_4H_ARGOY]  52.6 43.1 270 bottom
CON5300  -  [VX_MINI_PCI_67P_20_4H_H128]  245 89.9 0 bottom
CON5500  -  [VX_USB_9P_4HOLD_RA_SINGA]  260.9 45.2 90 top
CON5501  -  [VX_USB_9P_4HOLD_RA_SINGA]  260.9 72.6 90 top
CON5602  -  [VX_FPC_CON_28P_20_2H_AC_B]  36.5 180.1 0 bottom
CON6000  -  [VX_WTOB_10P_79_2HD_RA_CUIL]  243 17.57 180 bottom
CON6001  -  [VX_WTOB_7P_59_4HOLD_RA]  9.17 93.4 90 bottom
CON6002  -  [VX_SW_4P_146_S205_2HOLD_H63]  245.01 76.7 0 bottom
CON6003  -  [T_SW_4P_185X185_DAWNING]  25 61.18 90 bottom
CON6700  -  [VX_FPC_45P_20_2H_RA_ENTE_B]  7 72.75 90 bottom
CON6701  -  [VX_WTOB_5P_39_2HOLD_ENTE]  7 101.65 180 bottom
D300  -  [VX_ESD_2P_34_39X24_INPAQ]  178.97 149.68 180 top
D301  -  [VX_ESD_2P_34_39X24_INPAQ]  179.02 147.16 180 top
D302  -  [VX_ESD_2P_34_39X24_INPAQ]  179.02 145.84 180 top
D400  -  [VX_ESD_2P_34_39X24_INPAQ]  206.88 150.61 270 top
D401  -  [VX_ESD_2P_34_39X24_INPAQ]  208.53 148.72 0 top
D402  -  [VX_ESD_2P_34_39X24_INPAQ]  206.75 146.09 0 top
D1201  -  [T_SOD962]  262.05 24.67 90 top
D1202  -  [T_SOD962]  262.05 23.44 270 top
D1203  -  [T_SOD962]  262.05 23.33 270 bottom
D1204  -  [T_SOD962]  262.05 24.6 90 bottom
D1205  -  [T_SOD962]  264.19 27.4 270 bottom
D1206  -  [T_SOD962]  264.19 28.67 90 bottom
D1207  -  [T_SOD962]  262.05 28.66 90 top
D1208  -  [T_SOD962]  262.05 27.42 270 top
D1209  -  [VX_ESD_2P_34_39X24_INPAQ]  257.89 20.41 90 top
D2301  -  [VX_SOD323_H35]  183.06 73.47 180 top
D2801  -  [VX_SOT323]  223.84 58.25 90 bottom
D3101  -  [VX_VARISTOR_0402_H24]  178.32 31.08 180 bottom
D3102  -  [VX_VARISTOR_0402_H24]  180.54 31.08 0 bottom
D3104  -  [VX_SOT323]  194.11 24.6 90 top
D3400  -  [VX_ESD_2P_34_39X24_INPAQ]  259.05 148.43 270 top
D3600  -  [VX_ESD_2P_34_39X24_INPAQ]  18.36 71.49 90 bottom
D3601  -  [VX_SOD323_H35]  19.96 68.34 270 bottom
D4502  -  [VX_SOT323]  42.09 181.88 270 top
D4503  -  [VX_SOD323_H35]  38.53 182.47 0 top
D4504  -  [VX_SOD323_H35]  57.07 180.31 90 bottom
D4800  -  [VX_SOT323]  247.19 75.47 0 top
D5000  -  [VX_SOT323]  38.67 112.68 180 bottom
D5001  -  [VX_SOT323]  38.67 109.13 180 bottom
D5002  -  [VX_SOT323]  188.39 84.72 180 bottom
D5003  -  [VX_SOT323]  187 80.91 270 bottom
D5004  -  [VX_SOT323]  120.34 53.33 180 top
D5101  -  [VX_SOD123]  160.07 20.54 0 top
D5501  -  [VX_ESD_2P_33_39X24_H24]  255.32 41.97 270 bottom
D5502  -  [VX_ESD_2P_33_39X24_H24]  256.63 41.97 270 bottom
D5503  -  [VX_ESD_2P_33_39X24_H24]  255.88 71.44 270 bottom
D5504  -  [VX_ESD_2P_33_39X24_H24]  255.88 73.6 90 bottom
D5505  -  [VX_ESD_2P_33_39X24_H24]  256.34 56.86 90 top
D5506  -  [VX_ESD_2P_33_39X24_H24]  257.2 67.91 90 top
D5601  -  [VX_SOT323]  47.8 178.45 270 bottom
D6002  -  [VX_VARISTOR_0402_H24]  235.51 25.62 270 bottom
D6003  -  [VX_VARISTOR_0402_H24]  235.51 27.65 90 bottom
D6005  -  [VX_SOT23_H49]  228.27 23.21 180 bottom
D6006  -  [VX_SOT23_H49]  228.27 26.51 180 bottom
D7001  -  [VX_SOT323]  96.32 116.6 270 top
D7402  -  [VX_SOT323]  105.86 116.85 90 bottom
D8102  -  [VX_SOT23_H43]  244.02 65.42 270 top
D8103  -  [VX_SOT23_H43]  248.72 65.42 270 top
D8200  -  [VX_SOD323_H37]  138.74 63.39 0 bottom
D8300  -  [VX_SOD323_H37]  142.04 61.89 270 top
D8301  -  [VX_SOD323_H37]  141.78 66.72 270 top
D8700  -  [VX_SOD323_H37]  144.58 89.25 0 bottom
D8800  -  [VX_SOT323]  229.16 27.99 270 top
D8801  -  [VX_SOT323]  24.2 108.61 270 top
D8802  -  [VX_SOD323_H37]  218.62 41.24 90 bottom
D8900  -  [VX_SOD323_H37]  177.98 79.11 0 top
D9200  -  [VX_SOD323_H35]  131.88 52.04 180 top
D9201  -  [VX_SOD323_H37]  138.48 52.21 180 top
D9202  -  [VX_SOD323_H35]  142.88 52.21 180 top
D9400  -  [VX_SOD323_H37]  77.14 157.88 270 top
D9500  -  [VX_SOD323_H37]  124.9 61.18 180 top
D9600  -  [VX_SOD323_H37]  76.12 175.61 0 bottom
F4601  -  [VX_POLYSWITCH_2P_1206_H24]  254.81 105.76 90 top
F4800  -  [VX_POLYSWITCH_2P_1206_H24]  253.64 81.68 0 top
H11  -  [NB_H_RT419X335B335D118_P2_S]  265.2 58.9 0 top
H21  -  [NB_H_RT335X350CBD118_P2_S]  267.8 14.6 0 top
H31  -  [VX_H_ST335CB315D118_P2]  217.3 14.6 180 top
H32  -  [NB_H_RT335X315B315D118_P2_S]  21.9 182.7 180 top
H33  -  [VX_H_ST335CB315D118_P2]  264.5 156.9 180 bottom
H34  -  [VX_H_ST335CB315D118_P2]  255.5 156.9 90 bottom
H35  -  [NB_H_RT335X315B315D118_P2_S]  136 182.7 0 top
H36  -  [VX_H_ST335CB315D118_P2]  83.5 181.7 90 top
H51  -  [VX_H_CT276CB315D118_P2]  24.1 51.95 180 top
H52  -  [VX_H_CT276CB315D118_P2]  23.8 10 180 bottom
H53  -  [VX_H_CT276CB315D118_P2]  75.5 114.72 0 top
H54  -  [VX_H_CT276CB315D118_P2]  110.65 80.7 0 top
H55  -  [VX_H_CT276CB315D118_P2]  198 54.6 0 top
H56  -  [VX_H_CT276CB315D118_P2]  151 23.3 0 top
H60  -  [NB_NUT_CT256SB315D146_LF2]  142.1 135.27 180 bottom
H61  -  [NB_NUT_CT256SB315D146_LF2]  53.82 167.15 180 bottom
H62  -  [NB_NUT_CT256SBD146_H91_LF2]  245 118.25 180 bottom
H63  -  [NB_NUT_CT256SB315D146_LF2]  98.31 172.01 180 bottom
H64  -  [NB_NUT_CT256SB315D146_LF2]  15.34 134.86 180 bottom
H65  -  [NB_NUT_CT256SB315D146_LF2]  88.39 115.72 180 bottom
H66  -  [NB_NUT_CT256SB315D146_LF2]  62.54 117.68 180 bottom
H68  -  [NB_NUT_CT256SBD146_H205]  141.4 83.15 270 bottom
H69  -  [NB_NUT_CT256SBD146_H134_LF2]  141.15 43.1 180 bottom
H301  -  [HOLE_C63D63N]  178.5 151.4 0 top
H302  -  [HOLE_O63X102DO63X102N]  169.6 146 90 top
H401  -  [HOLE_O63X102DO63X102N]  199.6 151.7 90 bottom
H402  -  [HOLE_C63D63N]  209.4 146 0 bottom
H701  -  [VX_H_ST335CB315D118_P2]  166.25 180.7 180 bottom
H702  -  [VX_H_ST335CB315D118_P2]  216.25 172.9 180 bottom
H703  -  [HOLE_C102D102N]  216.25 179.9 0 top
H704  -  [HOLE_O134X102DO134X102N]  166.25 171.7 0 top
H800  -  [HOLE_C102D102N]  172.95 159.45 180 bottom
H803  -  [HOLE_O134X102DO134X102N]  198.05 159.45 180 bottom
H804  -  [VX_H_ST335CB315D118_P2]  166.25 159.45 180 bottom
H805  -  [VX_H_ST335CB315D118_P2]  203.75 159.45 180 bottom
H6901  -  [HOLE_O122X102DO122X102N]  76.5 181.7 270 bottom
H6902  -  [HOLE_C102D102N]  23.8 3.5 270 bottom
H6903  -  [HOLE_O122X102DO122X102N]  247.5 156.9 180 bottom
JP5601  -  [NB_OPEN2_5MIL_PT]  31.57 183.52 90 top
JP8050  -  [NB_PWR_FB_SHORT_PT]  45.39 165.5 0 top
JP8051  -  [NB_PWR_FB_SHORT_PT]  41.83 165.5 180 top
JP8052  -  [NB_PWR_FB_SHORT_PT]  31.4 165.92 180 top
JP8053  -  [NB_PWR_FB_SHORT_PT]  34.83 166.04 0 top
JP8054  -  [NB_PWR_FB_SHORT_PT]  63.42 160.16 90 top
JP8055  -  [NB_PWR_FB_SHORT_PT]  63.17 156.61 270 top
JP8056  -  [NB_PWR_FB_SHORT_PT]  77.78 169.05 0 bottom
JP8057  -  [NB_PWR_FB_SHORT_PT]  10.08 155.59 0 top
JP8058  -  [NB_PWR_FB_SHORT_PT]  6.53 155.84 180 top
JP8059  -  [NB_PWR_FB_SHORT_PT]  23.04 162.7 90 top
JP8060  -  [NB_PWR_FB_SHORT_PT]  23.04 159.15 270 top
JP8061  -  [NB_PWR_FB_SHORT_PT]  74.22 168.92 180 bottom
JP8100  -  [1MM_OPEN_5MIL_M1M2]  222.05 70.37 270 top
JP8101  -  [3MM_OPEN_5MIL_M1M2]  233.35 75.2 90 top
JP8102  -  [3MM_OPEN_5MIL_M1M2]  203.12 69.61 270 top
JP8103  -  [NB_PWR_FB_SHORT_PT]  223.11 78.2 270 bottom
JP8104  -  [NB_PWR_FB_SHORT_PT]  224.1 78.17 270 bottom
JP8105  -  [NB_PWR_FB_SHORT_PT]  197.51 81.2 180 bottom
JP8106  -  [1MM_OPEN_5MIL_M1M2]  218.44 82.14 0 top
JP8107  -  [1MM_OPEN_5MIL_M1M2]  252.65 65.42 0 top
JP8108  -  [3MM_OPEN_5MIL_M1M2]  203 74.44 270 top
JP8109  -  [3MM_OPEN_5MIL_M1M2]  202.87 79.47 270 top
JP8110  -  [3MM_OPEN_5MIL_M1M2]  236.02 70.12 180 top
JP8111  -  [3MM_OPEN_5MIL_M1M2]  240.72 69.61 180 top
JP8200  -  [NB_PWR_FB_SHORT_PT]  147.75 66.9 0 bottom
JP8202  -  [3MM_OPEN_5MIL_M1M2]  153.15 59.95 180 top
JP8300  -  [NB_PWR_FB_SHORT_PT]  132.11 58.49 0 top
JP8301  -  [1MM_OPEN_5MIL_M1M2]  128.96 57.93 270 top
JP8302  -  [3MM_OPEN_5MIL_M1M2]  109.46 71.39 270 top
JP8303  -  [NB_PWR_FB_SHORT_PT]  117.04 68.95 270 top
JP8304  -  [NB_PWR_FB_SHORT_PT]  117.68 69.33 0 top
JP8400  -  [1MM_OPEN_5MIL_M1M2]  167.95 27.57 90 top
JP8800  -  [3MM_OPEN_5MIL_M1M2]  255.45 12.79 90 top
JP8801  -  [NB_PWR_FB_SHORT_PT]  2.94 116.02 270 top
JP8802  -  [NB_PWR_FB_SHORT_PT]  2.94 114.25 90 top
JP8803  -  [3MM_OPEN_5MIL_M1M2]  256.16 17.11 90 top
JP8804  -  [NB_PWR_FB_SHORT_PT]  244.95 11.95 0 top
JP8805  -  [NB_PWR_FB_SHORT_PT]  246.74 11.9 180 top
JP8806  -  [3MM_OPEN_5MIL_M1M2]  17.46 111.19 270 top
JP8901  -  [3MM_OPEN_5MIL_M1M2]  155.25 92.68 90 bottom
JP8902  -  [3MM_OPEN_5MIL_M1M2]  155.25 92.68 270 top
JP9000  -  [NB_PWR_FB_SHORT_PT]  132.33 41.72 0 top
JP9300  -  [NB_OPEN2_5MIL_PT]  13.54 182.2 0 top
JP9301  -  [NB_OPEN2_5MIL_PT]  217.35 91.33 90 bottom
JP9302  -  [NB_OPEN2_5MIL_PT]  217.35 89.55 90 bottom
JP9303  -  [NB_OPEN2_5MIL_PT]  219.94 87.39 90 top
JP9400  -  [3MM_OPEN_5MIL_M1M2]  69.39 149.62 0 bottom
JP9401  -  [NB_PWR_FB_SHORT_PT]  71.09 161.76 270 bottom
JP9500  -  [3MM_OPEN_5MIL_M1M2]  108.76 62.12 90 top
JP9501  -  [NB_PWR_FB_SHORT_PT]  111.43 65.42 270 top
JP9502  -  [NB_PWR_FB_SHORT_PT]  112.07 64.91 180 top
JP9600  -  [2MM_OPEN_5MIL_M1M2]  92.25 168.88 180 top
JP9601  -  [NB_PWR_FB_SHORT_PT]  92.13 176.5 270 top
JP9602  -  [NB_PWR_FB_SHORT_PT]  89.59 169.51 90 top
L1101  -  [VX_INDUCTOR_2P_157X157_COIL]  248.16 42.38 90 top
L1106  -  [VX_L0603_H37_SMALL]  227.38 37.05 90 bottom
L1201  -  [VX_CHOKE_4P_49X39_MUR]  255.02 35.27 270 bottom
L1202  -  [VX_CHOKE_4P_49X39_MUR]  252.61 31.08 270 bottom
L3300  -  [VX_INDUCTOR_2P_118X118_MAG]  232.08 88.15 90 top
L3301  -  [VX_L0603_H37_SMALL]  223.27 90.92 0 bottom
L3302  -  [VX_L0603_H37_SMALL]  229.41 89.55 270 bottom
L3400  -  [VX_CHOKE_4P_79X47_FUKUI_H39]  252.65 137.3 0 bottom
L3401  -  [VX_CHOKE_4P_79X47_FUKUI_H39]  252.65 140.1 0 bottom
L3402  -  [VX_CHOKE_4P_79X47_FUKUI_H39]  252.65 142.89 0 bottom
L3403  -  [VX_CHOKE_4P_79X47_FUKUI_H39]  252.65 146.06 0 bottom
L3600  -  [VX_L0603_H37_SMALL]  21.11 83.63 270 bottom
L3601  -  [VX_L0603_H37_SMALL]  17.2 61.56 0 top
L3606  -  [VX_L0603_H37_SMALL]  13.23 75.98 90 top
L3607  -  [VX_L0603_H37_SMALL]  21.39 61.69 180 top
L3701  -  [VX_L0603_H37_SMALL]  194.49 34.89 180 bottom
L3702  -  [VX_L0603_H37_SMALL]  194.49 36.29 180 bottom
L3703  -  [VX_L0603_H37_SMALL]  196.52 32.22 180 bottom
L3704  -  [VX_L0603_H37_SMALL]  196.52 30.52 180 bottom
L4301  -  [VX_CHOKE_4P_79X47_FUKUI_H39]  92.13 180.23 270 bottom
L4302  -  [VX_CHOKE_4P_79X47_FUKUI_H39]  89.71 180.23 90 bottom
L4500  -  [VX_CHOKE_4P_79X47_FUKUI_H39]  54.28 175.02 90 bottom
L4501  -  [VX_CHOKE_4P_79X47_FUKUI_H39]  72.57 178.58 90 bottom
L4502  -  [VX_CHOKE_4P_79X47_FUKUI_H39]  69.01 177.94 90 bottom
L4503  -  [VX_CHOKE_4P_79X47_FUKUI_H39]  66.47 177.94 90 bottom
L4504  -  [VX_CHOKE_4P_79X47_FUKUI_H39]  63.93 177.94 90 bottom
L4505  -  [VX_CHOKE_4P_79X47_FUKUI_H39]  61.39 177.94 90 bottom
L4800  -  [VX_CHOKE_4P_39X49_QUIE_H24]  255.19 87.64 270 top
L4801  -  [VX_CHOKE_4P_39X49_QUIE_H24]  255.19 98.06 270 top
L4802  -  [VX_CHOKE_4P_39X49_QUIE_H24]  255.19 100.47 270 top
L4803  -  [VX_CHOKE_4P_39X49_QUIE_H24]  255.19 84.72 270 top
L5300  -  [VX_L0603_H37_SMALL]  240.59 90.31 90 top
L5301  -  [VX_CHOKE_4P_79X47_FUKUI_H39]  238.18 80.79 270 bottom
L5302  -  [VX_L0603_H37_SMALL]  240.59 93.99 270 top
L5500  -  [VX_CHOKE_4P_79X47_FUKUI_H39]  254.11 47.49 0 top
L5501  -  [VX_CHOKE_4P_79X47_FUKUI_H39]  255.87 44.76 270 bottom
L5502  -  [VX_CHOKE_4P_79X47_FUKUI_H39]  254.36 45.15 0 top
L5503  -  [VX_CHOKE_4P_79X47_FUKUI_H39]  251.89 72.02 0 top
L5504  -  [VX_CHOKE_4P_79X47_FUKUI_H39]  253.47 72.71 0 bottom
L5505  -  [VX_CHOKE_4P_79X47_FUKUI_H39]  251.93 69.35 0 top
L6001  -  [VX_L1812_H67]  17.32 102.3 90 top
L6002  -  [VX_L1812_H67]  21.45 102.32 90 top
L6700  -  [VX_L0603_H37_SMALL]  13.01 73.29 180 bottom
L6701  -  [VX_L0603_H37_SMALL]  13.01 71.9 180 bottom
L7100  -  [VX_L0603_SMALL]  104.11 165.59 90 bottom
L7201  -  [VX_L0603_H37_SMALL]  82.22 152.67 180 top
L7202  -  [VX_L0603_H37_SMALL]  93.14 166.72 0 top
L7203  -  [VX_L0603_H37_SMALL]  90.6 128.36 0 top
L7204  -  [VX_L0603_H37_SMALL]  89.21 130.44 270 top
L8000  -  [VX_INDUCTOR_2P_278X260_H118]  43.61 164.99 180 top
L8001  -  [VX_INDUCTOR_2P_278X260_H118]  33.2 165.11 0 top
L8002  -  [VX_INDUCTOR_2P_278X260_H118]  63.45 158.38 270 top
L8003  -  [VX_INDUCTOR_2P_278X260_H118]  8.31 156.35 0 top
L8004  -  [VX_INDUCTOR_2P_278X260_H118]  23.04 160.92 270 top
L8005  -  [VX_INDUCTOR_2P_274X260_H157]  76 168.92 180 bottom
L8100  -  [VX_CHOKE_2P_543X496]  231.32 70.12 270 bottom
L8101  -  [VX_CHOKE_2P_543X496]  205.66 72.4 180 bottom
L8200  -  [VX_INDUCTOR_2P_205X185]  146.65 72.1 0 bottom
L8300  -  [VX_INDUCTOR_2P_274X260]  113.5 71.48 180 bottom
L8700  -  [VX_INDUCTOR_2P_299X260_CYN]  119.43 91.58 90 bottom
L8701  -  [VX_INDUCTOR_2P_299X260_CYN]  128.73 91.45 90 bottom
L8702  -  [VX_INDUCTOR_2P_299X260_CYN]  144.7 112.31 180 bottom
L8800  -  [VX_INDUCTOR_2P_291X264]  239.32 15.46 270 top
L8900  -  [VX_INDUCTOR_2P_274X260_H157]  164.44 83.66 90 bottom
L9400  -  [VX_INDUCTOR_2P_205X185]  70.92 157.57 180 bottom
L9500  -  [VX_INDUCTOR_2P_291X264]  113.46 62.78 0 bottom
L9600  -  [VX_INDUCTOR_2P_150X150_CYN]  89.03 172.69 180 top
LC800  -  [VX_C0402_SMALL]  179.53 157.44 270 top
LC801  -  [VX_C0402_SMALL]  179.53 159.47 90 top
LC802  -  [VX_C0402_SMALL]  190.96 161.56 90 top
LC803  -  [VX_C0402_SMALL]  195.05 156.94 180 top
LLED800  -  [VX_LED_2P_39X20_EVERLIG]  178.3 159.45 90 bottom
LLED801  -  [VX_LED_2P_39X20_EVERLIG]  185.81 159.44 90 bottom
LLED802  -  [VX_LED_2P_39X20_EVERLIG]  192.3 159.45 90 bottom
LLED803  -  [VX_LED_2P_39X20_EVERLIG]  184.8 159.45 90 bottom
LQ800  -  [VX_SOT23_H44]  176.91 157.83 0 top
LQ801  -  [VX_SOT23_H44]  176.91 161.06 0 top
LQ802  -  [VX_SOT23_H44]  193.68 161.05 180 top
LQ803  -  [VX_SC70_S6]  192.21 158.05 270 top
LR800  -  [VX_R0603_H28_SMALL]  181.92 157.57 0 top
LR801  -  [VX_R0603_H28_SMALL]  179.71 161.38 270 top
LR802  -  [VX_R0603_H28_SMALL]  198.3 162.02 0 top
LR803  -  [VX_R0603_H28_SMALL]  172.54 161.69 180 top
LR804  -  [VX_R0402_SMALL]  195.05 157.92 180 top
NOREF  -  [unnamed]  269.46 191.62 0 top
NOREF#2  -  [#2]  176.69 181.85 0 top
NOREF#3  -  [#2]  91.49 40.1 0 top
NOREF#4  -  [unnamed#3]  252.95 191.62 0 top
NOREF#5  -  [unnamed#3]  15.89 179.78 0 top
NOREF#6  -  [unnamed#3]  261.42 12.16 0 top
NOREF#7  -  [unnamed#3]  21.13 191.62 0 top
NOREF#8  -  [unnamed]  164.47 168.26 0 top
NOREF#9  -  [unnamed]  4.62 191.62 0 top
NOREF#10  -  [unnamed#3]  25.29 20.18 0 top
NOREF#11  -  [unnamed#3]  212.97 191.62 0 top
NOREF#12  -  [#2]  175.17 168 0 top
NOREF#13  -  [#2]  74.55 -31.02 0 top
NOREF#14  -  [unnamed#3]  60.91 -2.92 0 top
NOREF#15  -  [unnamed]  4.62 -2.92 0 top
NOREF#16  -  [#2]  173.79 -1.65 0 top
NOREF#17  -  [unnamed#3]  31.29 -2.92 0 top
NOREF#18  -  [#2]  137.59 192.5 0 top
NOREF#19  -  [unnamed#3]  260.57 -2.92 0 top
NOREF#20  -  [#2]  57.2 38.83 0 top
NOREF#21  -  [unnamed]  269.46 -2.92 0 top
NOREF#22  -  [#2]  192.84 151.48 180 bottom
NOREF#23  -  [#2]  106.1 -1.65 180 bottom
NOREF#24  -  [unnamed#3]  26.21 191.62 180 bottom
NOREF#25  -  [#2]  209.47 149.83 180 bottom
NOREF#26  -  [#2]  172.22 162.23 180 bottom
NOREF#27  -  [unnamed#3]  60.91 191.62 180 bottom
NOREF#28  -  [unnamed#3]  247.87 191.62 180 bottom
NOREF#29  -  [unnamed#3]  12.67 60.23 180 bottom
NOREF#30  -  [unnamed#3]  212.97 -2.92 180 bottom
NOREF#31  -  [unnamed#3]  261.42 14.06 180 bottom
NOREF#32  -  [#2]  175.59 159.38 180 bottom
NOREF#33  -  [#2]  175.97 146.19 180 bottom
NOREF#34  -  [unnamed#3]  36.37 -2.92 180 bottom
NOREF#35  -  [#2]  184.15 149.65 180 bottom
NOREF#36  -  [#2]  137.59 192.5 180 bottom
NOREF#37  -  [unnamed#3]  257.1 148.3 180 bottom
NOREF#38  -  [unnamed#3]  255.49 -2.92 180 bottom
PC700  -  [VX_C0402_SMALL]  187.31 173.67 90 top
PC701  -  [VX_C0402_SMALL]  210.86 170.8 90 top
PCON700  -  [VX_FPC_8P_20_2H_RA_ACE_B]  173.25 174.65 180 top
PCON702  -  [VX_FPC_18P_20_2HLD_ACES]  207.16 179.23 180 top
PD700  -  [VX_ESD_2P_34_39X24_INPAQ]  187.61 168.09 180 top
PD701  -  [VX_ESD_2P_34_39X24_INPAQ]  196.44 174.64 270 top
PD702  -  [VX_ESD_2P_34_39X24_INPAQ]  210.43 173.69 0 top
PLED701  -  [VX_LED_2P_150X39_RA]  173.66 182.45 248 bottom
PLED702  -  [VX_LED_2P_150X39_RA]  209.11 176.5 90 bottom
PQ700  -  [VX_SOT23_H44]  199.39 173.81 180 top
PR700  -  [VX_R0402_SMALL]  185.62 173.19 180 top
PR701  -  [VX_R0603_H28_SMALL]  179.88 173.32 270 top
PR702  -  [VX_R0402_SMALL]  210.43 172.63 0 top
PR703  -  [VX_R0603_H28_SMALL]  198.84 176.03 180 top
PSR701  -  [VX_R0402_SMALL_SHORT]  185.6 174.1 180 top
PSW1700  -  [VX_SW_4P_2HOLD_130X130]  191.25 168.3 180 bottom
PU701  -  [VX_SC59_DII1]  209.25 181.5 270 bottom
Q0702  -  [VX_SOT23_H43]  5.39 153.81 180 bottom
Q1201  -  [VX_SOT23_H43]  223.32 61.69 90 top
Q1202  -  [VX_SOT23_H43]  220.07 62.2 90 top
Q1302  -  [VX_SOT363_NB]  216.46 48.02 180 top
Q2301  -  [VX_SOT23_H43]  165.53 29.53 90 bottom
Q3100  -  [VX_SOT23_H43]  150.93 29.43 90 top
Q3102  -  [VX_SOT23_H43]  154.74 30.07 180 top
Q3107  -  [VX_SOT23_2D4_H44]  193.22 39.08 270 bottom
Q3108  -  [VX_SOT23_2D4_H44]  144.83 36.42 180 top
Q3109  -  [VX_SOT23_2D4_H44]  137.85 31.46 270 top
Q3110  -  [VX_SOT23_2D4_H44]  141.15 36.42 180 top
Q3111  -  [VX_SOT23_2D4_H44]  137.47 36.42 180 top
Q3601  -  [VX_SC70_S6]  2.72 70.45 180 top
Q3602  -  [VX_SOT23_H43]  2.72 66.01 90 top
Q4501  -  [VX_SOT23_2D4_H44]  48.34 172.46 0 bottom
Q4601  -  [VX_SOT23_H43]  257.1 94.2 270 top
Q4801  -  [VX_SOT23_H43]  247.96 78.5 180 top
Q4802  -  [VX_SOT23_H43]  253.42 74.82 180 top
Q4803  -  [VX_SOT23_H43]  253.42 78.12 180 top
Q4804  -  [VX_SOT23_H43]  247.45 82.39 90 top
Q4805  -  [VX_SOT23_2D4_H43]  253.16 94.2 0 top
Q5001  -  [VX_SOT23_H43]  166.42 76.29 180 top
Q5101  -  [VX_SOT23_2D4_H44]  159.31 23.46 270 top
Q5102  -  [VX_SOT23_H43]  158.38 26.85 0 top
Q5300  -  [VX_SOT23_2D4_H43]  243.51 88.41 90 top
Q5301  -  [VX_SOT23_H43]  237.54 83.53 180 top
Q5302  -  [VX_SOT23_H43]  237.54 80.1 180 top
Q5700  -  [VX_SOT23_H43]  152.71 133.24 90 bottom
Q5701  -  [VX_SOT23_H43]  156.26 133.24 90 bottom
Q5702  -  [VX_SOT23_H43]  149.4 133.24 270 bottom
Q5703  -  [VX_SOT23_H43]  156.26 137.68 270 bottom
Q5704  -  [VX_SOT23_H43]  152.71 137.68 90 bottom
Q5705  -  [VX_SOT23_H43]  149.4 137.68 270 bottom
Q6001  -  [VX_SOT23_H43]  254.18 65.67 180 bottom
Q6701  -  [VX_SOT23_H43]  3.99 74.52 0 top
Q7000  -  [VX_SOT23_H43]  84.76 131.59 0 bottom
Q7201  -  [VX_SOT23_H43]  245.92 97.76 180 top
Q7202  -  [VX_SOT23_2D4_H43]  237.92 116.81 270 top
Q7203  -  [VX_SOT23_2D4_H43]  237.92 120.49 270 top
Q7400  -  [VX_SOT23_H43]  99.37 111.14 90 bottom
Q7401  -  [VX_SOT23_H43]  81.46 119.78 90 bottom
Q7402  -  [VX_SOT23_H43]  81.46 115.46 90 bottom
Q7403  -  [VX_SOT23_H43]  99.62 116.6 90 top
Q7404  -  [VX_SOT23_H43]  105.97 110.12 270 bottom
Q7405  -  [VX_SOT23_H43]  102.67 110.12 270 bottom
Q7600  -  [VX_SOT23_2D4_H43]  134.43 175.92 270 top
Q7700  -  [VX_SOT23_2D4_H43]  157.15 166.21 0 bottom
Q7800  -  [VX_SOT23_2D4_H43]  156.77 127.09 0 bottom
Q7900  -  [VX_SOT23_2D4_H43]  137.21 115.66 90 top
Q8001  -  [VX_SI7850DP]  83.49 166.77 180 bottom
Q8002  -  [VX_SI7850DP]  84.38 174.39 90 bottom
Q8100  -  [VX_SOP_8P_SPE_FAIRCHILD]  221.79 64.53 180 bottom
Q8101  -  [VX_SOP_8P_SPE_FAIRCHILD]  208.71 62.63 270 bottom
Q8106  -  [VX_SC70_S6]  217.22 86.76 180 top
Q8300  -  [VX_SI7850DP]  122.35 74.31 90 bottom
Q8301  -  [VX_SI7850DP]  122.91 66.56 270 bottom
Q8701  -  [VX_SI7850DP]  121.34 84.42 270 top
Q8703  -  [VX_SI7850DP]  120.19 83.91 90 bottom
Q8704  -  [VX_SI7850DP]  111.94 88.85 180 bottom
Q8705  -  [VX_SI7850DP]  128.96 85.56 180 top
Q8707  -  [VX_SI7850DP]  127.94 82.26 180 bottom
Q8708  -  [VX_SI7850DP]  134.04 82.01 180 bottom
Q8709  -  [VX_SI7850DP]  152.75 104.6 180 top
Q8711  -  [VX_SI7850DP]  155.37 104.23 270 bottom
Q8712  -  [VX_SI7850DP]  153.93 112.11 270 bottom
Q8800  -  [VX_SOIC_8P_50_217X236]  248.03 17.11 270 top
Q8801  -  [VX_SOIC_8P_50_197X236_IDT]  16.05 116.35 270 top
Q8802  -  [VX_SOIC_8P_50_197X236_IDT]  8.05 118 90 top
Q8803  -  [VX_SOIC_8P_50_197X236]  231.78 20.92 90 top
